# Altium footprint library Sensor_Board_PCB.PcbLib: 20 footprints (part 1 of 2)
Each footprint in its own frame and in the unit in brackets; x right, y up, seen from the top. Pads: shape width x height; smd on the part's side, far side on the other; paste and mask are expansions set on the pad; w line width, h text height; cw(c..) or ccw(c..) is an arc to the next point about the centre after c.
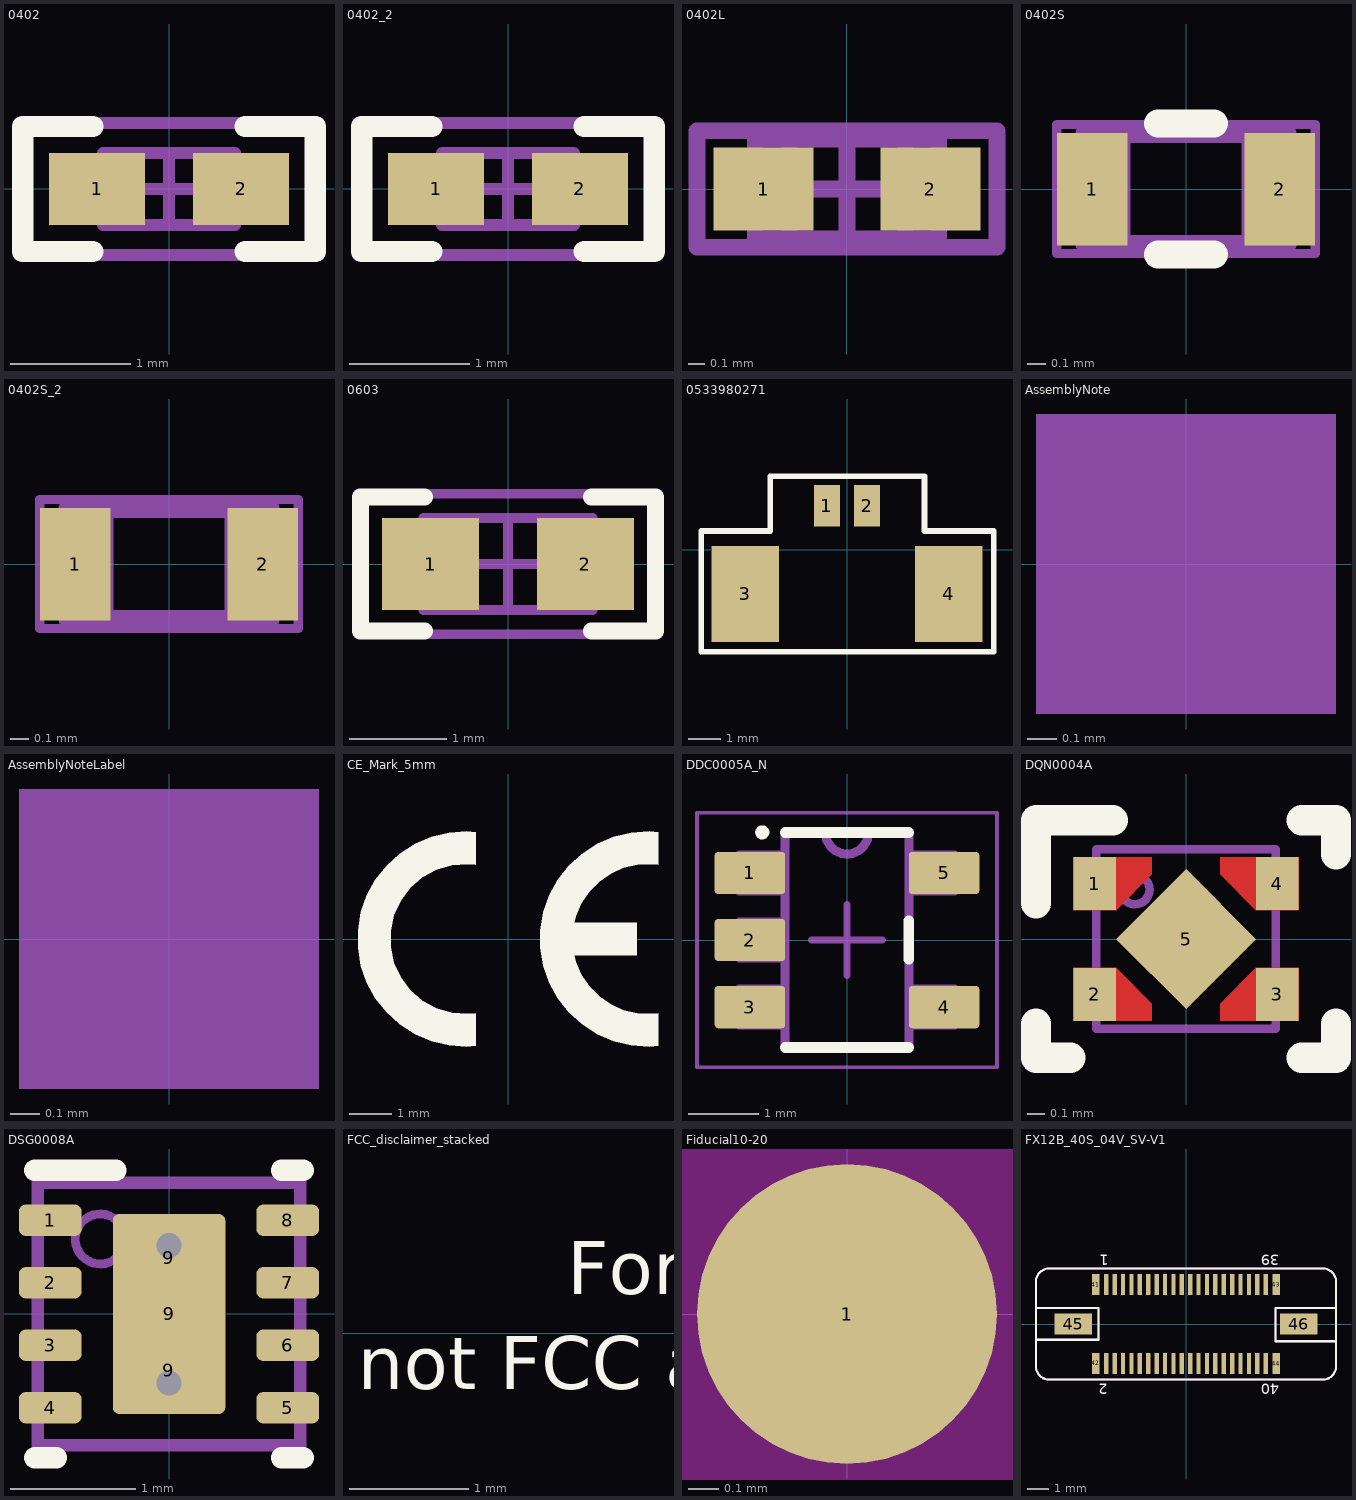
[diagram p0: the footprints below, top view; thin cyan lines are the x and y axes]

## 0402 [mm] "0402 from SM-752 data"
height 0.6
pads (2):
  rect 0.8x0.6 smd: 1(-0.6,0) 2(0.6,0)
Top Overlay:
  lines w0.178: -0.635,-0.521 -1.219,-0.521 -1.219,0.521 -0.635,0.521 ; 0.635,-0.521 1.219,-0.521 1.219,0.521 0.635,0.521
Mechanical 5:
  lines w0.1: -1.25,-0.55 -1.25,0.55 1.25,0.55 1.25,-0.55 -1.25,-0.55
  text ".Designator" at -0.406,-0.279 h0.46
Mechanical 13:
  lines w0.1: -0.35,-0.3 -0.35,0.3 ; 0.35,-0.3 0.35,0.3 ; -0.55,-0.3 0.55,-0.3 0.55,0.3 -0.55,0.3 -0.55,-0.3
Mechanical 15:
  lines w0.1: -0.3,0 0.3,0 ; 0,-0.3 0,0.3 ; -1.25,-0.55 1.25,-0.55 1.25,0.55 -1.25,0.55 -1.25,-0.55
3D body: height 0.6, standoff 0, extent 0.351,-0.299 0.549,0.299
3D body: height 0.6, standoff 0, extent -0.349,-0.299 0.349,0.299
3D body: height 0.6, standoff 0, extent -0.549,-0.299 -0.351,0.299

## 0402_2 [mm]
pads (2):
  rect 0.8x0.6 smd: 1(-0.6,0) 2(0.6,0)
Top Overlay:
  lines w0.178: -0.635,-0.521 -1.219,-0.521 -1.219,0.521 -0.635,0.521 ; 0.635,-0.521 1.219,-0.521 1.219,0.521 0.635,0.521
Mechanical 5:
  lines w0.1: -1.25,-0.55 1.25,-0.55 1.25,0.55 -1.25,0.55 -1.25,-0.55
  text ".Designator" at 0.374,0.229 h0.46
Mechanical 13:
  lines w0.1: -0.35,-0.3 -0.35,0.3 ; 0.35,-0.3 0.35,0.3 ; -0.55,-0.3 -0.55,0.3 0.55,0.3 0.55,-0.3 -0.55,-0.3
Mechanical 15:
  lines w0.1: -0.3,0 0.3,0 ; 0,-0.3 0,0.3 ; -1.25,-0.55 -1.25,0.55 1.25,0.55 1.25,-0.55 -1.25,-0.55
3D body: height 0.6, standoff 0, extent -0.549,-0.299 -0.351,0.299
3D body: height 0.6, standoff 0, extent -0.349,-0.299 0.349,0.299
3D body: height 0.6, standoff 0, extent 0.351,-0.299 0.549,0.299

## 0402L [mm] "0402 from SM-752 data"
height 0.6
pads (2):
  rect 0.6x0.5 smd: 1(-0.5,0) 2(0.5,0)
Mechanical 5:
  lines w0.1: -0.9,-0.35 0.9,-0.35 0.9,0.35 -0.9,0.35 -0.9,-0.35
  text ".Designator" at -0.656,-0.229 h0.46
Mechanical 13:
  lines w0.1: -0.35,-0.3 -0.35,0.3 ; 0.35,-0.3 0.35,0.3 ; -0.55,-0.3 -0.55,0.3 0.55,0.3 0.55,-0.3 -0.55,-0.3
Mechanical 15:
  lines w0.1: -0.3,0 0.3,0 ; 0,-0.3 0,0.3 ; -0.9,-0.35 -0.9,0.35 0.9,0.35 0.9,-0.35 -0.9,-0.35
3D body: height 0.6, standoff 0, extent -0.549,-0.299 -0.351,0.299
3D body: height 0.6, standoff 0, extent -0.349,-0.299 0.349,0.299
3D body: height 0.6, standoff 0, extent 0.351,-0.299 0.549,0.299

## 0402S [mil] "Based on C0402S footprint from PADS legacy"
height 23.62
pads (2):
  rect 15x24 smd: 1(-20,0) 2(20,0)
Top Overlay:
  lines w6: -6,-14 6,-14 ; -6,14 6,14
Mechanical 5:
  lines w1.97: -27.56,-13.78 -27.56,13.78 27.56,13.78 27.56,-13.78 -27.56,-13.78
  text ".Designator" at 33,-8 h18
Mechanical 13:
  lines w3.94: -13.78,-11.81 -13.78,11.81 ; 13.78,-11.81 13.78,11.81 ; -21.65,-11.81 21.65,-11.81 21.65,11.81 -21.65,11.81 -21.65,-11.81
3D body: height 23.62, standoff 0, extent 13.8,-11.79 21.63,11.79
3D body: height 23.62, standoff 0, extent -13.76,-11.79 13.76,11.79
3D body: height 23.62, standoff 0, extent -21.63,-11.79 -13.8,11.79

## 0402S_2 [mil]
pads (2):
  rect 15x24 smd: 1(-20,0) 2(20,0)
Mechanical 5:
  lines w1.97: -27.56,-13.78 -27.56,13.78 27.56,13.78 27.56,-13.78 -27.56,-13.78
  text ".Designator" at 13.61,9 h18
Mechanical 13:
  lines w3.94: -13.78,-11.81 -13.78,11.81 ; 13.78,-11.81 13.78,11.81 ; -21.65,-11.81 21.65,-11.81 21.65,11.81 -21.65,11.81 -21.65,-11.81
3D body: height 23.62, standoff 0, extent 13.8,-11.79 21.63,11.79
3D body: height 23.62, standoff 0, extent -13.76,-11.79 13.76,11.79
3D body: height 23.62, standoff 0, extent -21.63,-11.79 -13.8,11.79

## 0603 [mm] "0603 from SM-752 data"
height 1
pads (2):
  rect 1x0.95 smd: 1(-0.8,0) 2(0.8,0)
Top Overlay:
  lines w0.178: -0.864,-0.691 -1.524,-0.691 -1.524,0.693 -0.864,0.693 ; 0.864,-0.691 1.524,-0.691 1.524,0.693 0.864,0.693
Mechanical 5:
  lines w0.1: -1.55,-0.725 -1.55,0.725 1.55,0.725 1.55,-0.725 -1.55,-0.725
  text ".Designator" at 0.838,0.368 h0.46
Mechanical 13:
  lines w0.1: -0.55,-0.475 -0.55,0.475 ; 0.55,-0.475 0.55,0.475 ; -0.875,-0.475 0.875,-0.475 0.875,0.475 -0.875,0.475 -0.875,-0.475
Mechanical 15:
  lines w0.1: -0.475,0 0.475,0 ; 0,-0.475 0,0.475 ; -1.55,-0.725 1.55,-0.725 1.55,0.725 -1.55,0.725 -1.55,-0.725
3D body: height 1, standoff 0, extent -0.874,-0.474 -0.551,0.474
3D body: height 1, standoff 0, extent -0.549,-0.474 0.549,0.474
3D body: height 1, standoff 0, extent 0.551,-0.474 0.874,0.474

## 0533980271 [mm] "Molex PicoBlade 2 pos from documents no. SD-53398-033 dated 2006-04-02"
height 4.7
pads (4):
  rect 0.8x1.3 smd: 1(-0.625,1.375) 2(0.625,1.375)
  rect 2.1x3 smd: 3(-3.175,-1.375) 4(3.175,-1.375)
Top Overlay:
  lines w0.178: -4.547,-3.172 4.572,-3.172 4.572,0.588 2.413,0.588 2.413,2.289 0.489,2.289 -1.429,2.289 -2.388,2.289 -2.388,0.588 -4.547,0.588 -4.547,-3.172
Mechanical 5:
  lines w0.127: -4.547,-3.172 -4.547,0.588 -2.388,0.588 -2.388,2.289 -1.429,2.289 0.489,2.289 2.413,2.289 2.413,0.588 4.572,0.588 4.572,-3.172 -4.547,-3.172
  text ".Designator" at -0.279,-0.613 h0.46
3D body "533980271.stp": height 4.8, standoff 0, extent -3.86,-2.439 3.79,1.761

## AssemblyNote [mil] "Assembly Note"
Mechanical 5:
  rectangle: -20,-20 20,20
  text ".Comment" at 45,-20 h18
  text ".Designator" at -165,-20 h18

## AssemblyNoteLabel [mil] "Assembly Note for PCB Labels"
Mechanical 5:
  rectangle: -20,-20 20,20
  text ".Designator" at -165,-20 h18
  text "Install label in silkscreened box after final wash.  Text shall be 8 pt font.  Text shall be per the Label Table in the PDF schematic." at 45,-20 h18

## CE_Mark_5mm [mil] "Minimum text height for CE Mark"
height 157.48
Top Overlay:
  region: -29.53,-97.93 -37.73,-98.76 -54.18,-97.65 -70.21,-93.83 -85.39,-87.39 -99.28,-78.52 -111.51,-67.46 -121.72,-54.53 -129.65,-40.07 -135.05,-24.5 -137.8,-8.24 -137.8,8.24 -135.05,24.5 -129.65,40.07 -121.72,54.53 -111.51,67.46 -99.28,78.52 -85.39,87.39 -70.21,93.83 -54.18,97.65 -37.73,98.76 -29.53,97.93 -29.53,68.19 -36.88,68.85 -51.57,67.81 -65.71,63.66 -78.65,56.61 -89.78,46.96 -98.62,35.17 -104.74,21.76 -107.87,7.37 -107.87,-7.37 -104.74,-21.76 -98.62,-35.17 -89.78,-46.96 -78.65,-56.61 -65.71,-63.66 -51.57,-67.81 -36.88,-68.85 -29.53,-68.19
  region: 137.79,-68.19 131.38,-68.81 118.5,-68.25 105.96,-65.29 94.19,-60.06 83.6,-52.72 74.56,-43.54 67.39,-32.84 62.33,-20.99 60.66,-14.76 118.11,-14.76 118.11,14.76 60.66,14.76 62.33,20.99 67.39,32.84 74.56,43.54 83.6,52.72 94.19,60.06 105.96,65.29 118.5,68.25 131.38,68.81 137.79,68.19 137.79,97.93 129.59,98.76 113.15,97.65 97.11,93.83 81.93,87.39 68.04,78.52 55.81,67.46 45.6,54.53 37.68,40.07 32.27,24.5 29.53,8.24 29.53,-8.24 32.27,-24.5 37.68,-40.07 45.6,-54.53 55.81,-67.46 68.04,-78.52 81.93,-87.39 97.11,-93.83 113.15,-97.65 129.59,-98.76 137.79,-97.93

## DDC0005A_N [mm]
height 1.1
pads (5):
  rrect17% 1x0.6 smd: 1(-1.375,0.95) 2(-1.375,0) 3(-1.375,-0.95) 4(1.375,-0.95) 5(1.375,0.95)
Top Overlay:
  circle w0.1: c-1.2,1.525 r0.05
  lines w0.152: -0.876,-1.524 0.876,-1.524 ; -0.876,1.524 0.876,1.524 ; 0.876,-0.274 0.876,0.274
Mechanical 5:
  lines w0.127: -0.305,1.524 ccw(c0,1.524) 0.305,1.524 ; -1.524,-1.204 -1.524,-0.696 -0.876,-0.696 -0.876,-1.204 -1.524,-1.204 ; -1.524,-0.254 -1.524,0.254 -0.876,0.254 -0.876,-0.254 -1.524,-0.254 ; -1.524,0.696 -1.524,1.204 -0.876,1.204 -0.876,0.696 -1.524,0.696 ; -0.876,-1.524 0.876,-1.524 0.876,1.524 -0.876,1.524 -0.876,-1.524 ; 0.876,-1.204 0.876,-0.696 1.524,-0.696 1.524,-1.204 0.876,-1.204 ; 0.876,0.696 0.876,1.204 1.524,1.204 1.524,0.696 0.876,0.696
  text ".Designator" at 0.432,0.155 h0.46
Mechanical 15:
  lines w0.05: -2.125,-1.8 2.125,-1.8 2.125,1.8 -2.125,1.8 -2.125,-1.8
  lines w0.1: -0.5,0 0.5,0 ; 0,-0.5 0,0.5
3D body "DDC0005A.stp": height 1.1, standoff 0, extent -1.406,-1.45 1.406,1.45

## DQN0004A [mm] "SON, 0.65mm pitch"
height 0.4
pads (5):
  rect 0.25x0.31 smd paste-1 mask-0.31: 1(-0.535,0.325) 2(-0.535,-0.325) 3(0.535,-0.325) 4(0.535,0.325)
  rect 0.58x0.58 smd rot 45 paste-0.065 mask-0.05: 5(0,0)
Top Layer:
  region: -0.66,0.48 -0.2,0.48 -0.2,0.379 -0.409,0.17 -0.66,0.17
  region: 0.66,0.48 0.2,0.48 0.2,0.379 0.409,0.17 0.66,0.17
  region: 0.66,-0.48 0.2,-0.48 0.2,-0.379 0.409,-0.17 0.66,-0.17
  region: -0.66,-0.48 -0.2,-0.48 -0.2,-0.379 -0.409,-0.17 -0.66,-0.17
Top Overlay:
  lines w0.178: -0.88,-0.496 -0.88,-0.696 -0.68,-0.696 ; -0.88,0.21 -0.88,0.696 -0.43,0.696 ; 0.68,-0.696 0.88,-0.696 0.88,-0.496 ; 0.68,0.696 0.88,0.696 0.88,0.496
Top Paste:
  region: -0.65,-0.43 -0.25,-0.43 -0.25,-0.4 -0.43,-0.22 -0.65,-0.22
  region: 0.65,-0.43 0.25,-0.43 0.25,-0.4 0.43,-0.22 0.65,-0.22
  region: 0.65,0.43 0.25,0.43 0.25,0.4 0.43,0.22 0.65,0.22
  region: -0.65,0.43 -0.25,0.43 -0.25,0.4 -0.43,0.22 -0.65,0.22
Mechanical 5:
  circle w0.05: c-0.3,0.29 r0.086
  lines w0.05: -0.525,-0.525 -0.525,0.525 0.525,0.525 0.525,-0.525 -0.525,-0.525
  text ".Designator" at 0.432,-0.686 h0.46
3D body: height 0.4, standoff 0, extent -0.525,-0.525 0.525,0.525
3D body: height 0.42, standoff 0.2, extent -0.386,0.204 -0.214,0.376

## DSG0008A [mm] "SON, 8-Leads, Body 2x2mm, Pitch 0.5mm, Thermal Pad 1.6x0.9mm, TI Recommended"
height 0.8
pads (11):
  rrect40% 0.5x0.25 smd: 1(-0.95,0.75) 2(-0.95,0.25) 3(-0.95,-0.25) 4(-0.95,-0.75) 5(0.95,-0.75) 6(0.95,-0.25) 7(0.95,0.25) 8(0.95,0.75)
  rrect50% 0.9x0.7 on Top Paste: 9(0,0.45) 9(0,-0.45)
  rrect11% 0.9x1.6 smd paste-0.45: 9(0,0)
via 0,-0.55 diameter 0.5 hole 0.2
via 0,0.55 diameter 0.5 hole 0.2
Top Overlay:
  lines w0.17: -1.075,-1.15 -0.9,-1.15 ; -1.075,1.15 -0.425,1.15 ; 0.9,-1.15 1.075,-1.15 ; 0.9,1.15 1.075,1.15
Mechanical 5:
  circle w0.07: c-0.55,0.6 r0.2
  lines w0.1: -1.05,-1.05 1.05,-1.05 1.05,1.05 -1.05,1.05 -1.05,-1.05
  text ".Designator" at 0.402,0.027 h0.46
3D body "DSG0008A.stp": height 0.77, standoff 0, extent -1,-1 1,1

## FCC_disclaimer_stacked [mil]
height 216.54
Top Overlay:
  text "For evaluation only;" at -229.68,7.01 h30
  text "not FCC approved for resale." at -299.05,-24.38 h30

## Fiducial10-20 [mm]
height 4
pads (1):
  round 1 smd mask+0.5: 1(0,0)
Top Layer keep-out:
  circle w1.178: c0,0 r0.5

## FX12B_40S_04V_SV-V1 [mm] "FX12B_40S_04V_SV-V1"
pads (46):
  rect 0.203x1 smd: 1(-3.8,1.88) 2(-3.8,-1.88) 3(-3.4,1.88) 4(-3.4,-1.88) 5(-3,1.88) 6(-3,-1.88) 7(-2.6,1.88) 8(-2.6,-1.88) 9(-2.2,1.88) 10(-2.2,-1.88) 11(-1.8,1.88) 12(-1.8,-1.88) 13(-1.4,1.88) 14(-1.4,-1.88) 15(-1,1.88) 16(-1,-1.88) 17(-0.6,1.88) 18(-0.6,-1.88) 19(-0.2,1.88) 20(-0.2,-1.88) 21(0.2,1.88) 22(0.2,-1.88) 23(0.6,1.88) 24(0.6,-1.88) 25(1,1.88) 26(1,-1.88) 27(1.4,1.88) 28(1.4,-1.88) 29(1.8,1.88) 30(1.8,-1.88) 31(2.2,1.88) 32(2.2,-1.88) 33(2.6,1.88) 34(2.6,-1.88) 35(3,1.88) 36(3,-1.88) 37(3.4,1.88) 38(3.4,-1.88) 39(3.8,1.88) 40(3.8,-1.88)
  rect 0.37x1 smd: 41(-4.3,1.88) 42(-4.3,-1.88) 43(4.3,1.88) 44(4.3,-1.88)
  rect 1.8x1 smd: 45(-5.375,0) 46(5.375,0)
Top Overlay:
  lines w0.1: -7.13,-0.75 -4.17,-0.75 -4.17,0.77 -7.13,0.77 ; 7.13,-0.82 4.26,-0.82 4.26,0.76 7.14,0.76 ; -7.15,-2.015 ccw(c-6.515,-2.015) -6.515,-2.65 6.515,-2.65 ccw(c6.515,-2.015) 7.15,-2.015 7.15,2.015 ccw(c6.515,2.015) 6.515,2.65 -6.515,2.65 ccw(c-6.515,2.015) -7.15,2.015 -7.15,-2.015
  text "1" at -3.683,3.302 h0.51
  text "2" at -3.72,-2.851 h0.51
  text "39" at 4.445,3.302 h0.51
  text "40" at 4.445,-2.851 h0.51
Mechanical 5:
  lines w0.1: -7.13,-0.75 -4.17,-0.75 -4.17,0.77 -7.13,0.77 ; 7.13,-0.82 4.26,-0.82 4.26,0.76 7.14,0.76 ; -7.15,-2.015 ccw(c-6.515,-2.015) -6.515,-2.65 6.515,-2.65 ccw(c6.515,-2.015) 7.15,-2.015 7.15,2.015 ccw(c6.515,2.015) 6.515,2.65 -6.515,2.65 ccw(c-6.515,2.015) -7.15,2.015 -7.15,-2.015
  text ".Designator" at 1.068,0.77 h0.46
  text "1" at -3.683,3.302 h0.46
Mechanical 15:
  text "34" at 2.6,-2.888 h0.64
  text "22" at 0.2,-2.888 h0.64
  text "7" at -2.6,1.126 h0.64
  text "36" at 3,-2.888 h0.64
  text "38" at 3.4,-2.888 h0.64
  text "17" at -0.6,0.872 h0.64
  text "28" at 1.4,-2.888 h0.64
  text "5" at -3,1.126 h0.64
  text "30" at 1.8,-2.888 h0.64
  text "14" at -1.4,-2.888 h0.64
  text "8" at -2.6,-2.634 h0.64
  text "24" at 0.6,-2.888 h0.64
  text "18" at -0.6,-2.888 h0.64
  text "16" at -1,-2.888 h0.64
  text "4" at -3.4,-2.634 h0.64
  text "9" at -2.2,1.126 h0.64
  text "39" at 3.8,0.872 h0.64
  text "40" at 3.8,-2.888 h0.64
  text "1" at -3.8,1.126 h0.64
  text "42" at -4.12,-3.738 h0.64
  text "45" at -5.375,-0.508 h0.64
  text "32" at 2.2,-2.888 h0.64
  text "26" at 1,-2.888 h0.64
  text "20" at -0.2,-2.888 h0.64
  text "44" at 4.48,-3.738 h0.64
  text "43" at 5.47,1.422 h0.64
  text "46" at 5.375,-0.508 h0.64
  text "41" at -4.95,1.382 h0.64
  text "2" at -3.8,-2.634 h0.64
  text "6" at -3,-2.634 h0.64
  text "37" at 3.4,0.872 h0.64
  text "35" at 3,0.872 h0.64
  text "33" at 2.6,0.872 h0.64
  text "31" at 2.2,0.872 h0.64
  text "3" at -3.4,1.126 h0.64
  text "29" at 1.8,0.872 h0.64
  text "27" at 1.4,0.872 h0.64
  text "25" at 1,0.872 h0.64
  text "23" at 0.6,0.872 h0.64
  text "21" at 0.2,0.872 h0.64
  text "19" at -0.2,0.872 h0.64
  text "15" at -1,0.872 h0.64
  text "13" at -1.4,0.872 h0.64
  text "12" at -1.8,-2.888 h0.64
  text "11" at -1.8,0.872 h0.64
  text "10" at -2.2,-2.888 h0.64
3D body: height 3.81, standoff 0, extent -7.2,-2.7 7.2,2.7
